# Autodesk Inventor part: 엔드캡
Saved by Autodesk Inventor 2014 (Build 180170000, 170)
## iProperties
Created: 2026-01
Part Number: 엔드캡
Material: 일반
Document SubType Name: Modeling
Designer: dg
Density: 1 g/cm^3
Appearance: 기본값
Author: dg
Author: jhkim
Creation Date: 2026-01-09
Sending System: Autodesk Inventor 2026
Preprocessor: ST-DEVELOPER v20.1
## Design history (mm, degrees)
node "엔드캡1"
node "솔리드1"
node "기준1"
